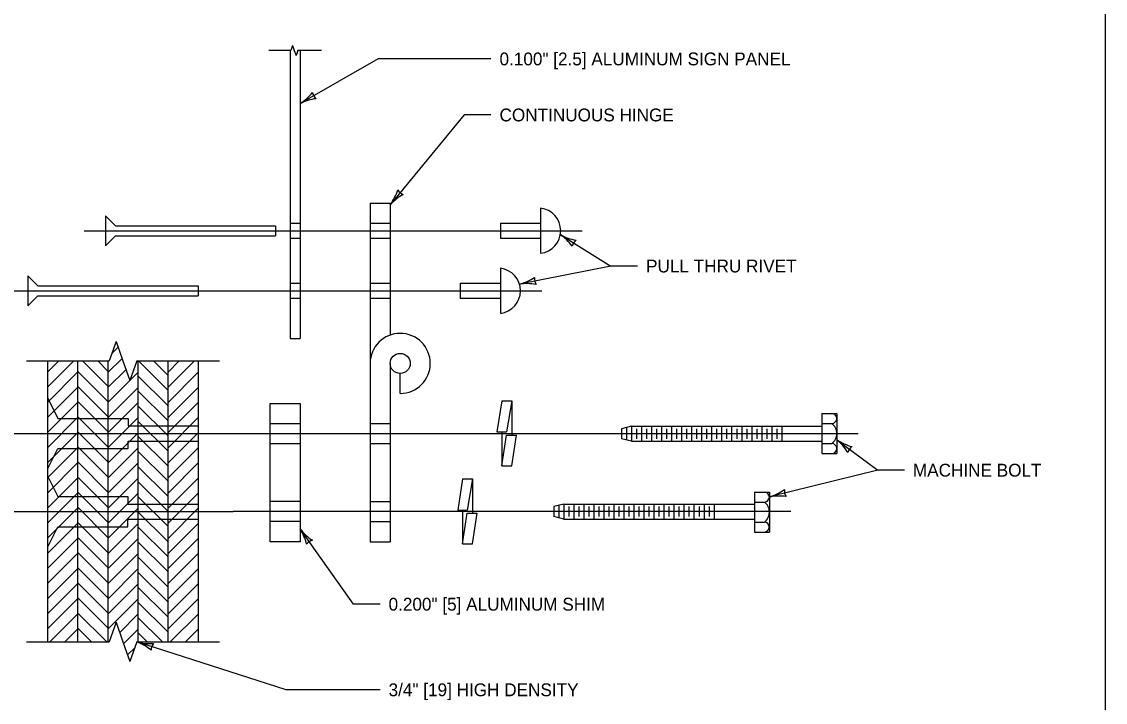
# Model space of a CAD drawing. Extents: x 49991.4 to 50021, y 49987.6 to 50011.4.
# Drawn here: x 50011.68 to 50016.75, y 49990.65 to 49993.84 of the extents above; entities that cross this region are included whole.
import ezdxf

# ---------------------------------------------------------------- set-up
doc = ezdxf.new("R2010")
doc.units = 0
for name, color, linetype in [('Level 1', 7, 'Continuous'), ('Level 2', 7, 'Continuous'), ('Level 3', 7, 'Continuous'), ('Level 4', 7, 'Continuous'), ('Level 5', 7, 'Continuous'), ('Level 6', 7, 'Continuous')]:
    doc.layers.add(name, color=color, linetype=linetype)

msp = doc.modelspace()

# ---------------------------------------------------------------- linework, layer by layer
at = {"layer": 'Level 1'}
for p, q in [((50012.9345, 49993.7046), (50012.9345, 49992.3569)), ((50012.9813, 49993.7046), (50012.9813, 49992.3569)), ((50013.3091, 49992.9898), (50013.4029, 49992.9898)), ((50013.3091, 49992.9898), (50013.3091, 49991.4053)), ((50013.4029, 49992.9898), (50013.4029, 49992.3724)), ((50012.0697, 49992.9311), (50012.0697, 49992.8609)), ((50012.1166, 49992.8843), (50012.0697, 49992.9311)), ((50014.1071, 49992.9664), (50014.1071, 49992.7554)), ((50012.1166, 49992.8843), (50012.8666, 49992.8843)), ((50012.8666, 49992.8843), (50012.8666, 49992.8375)), ((50012.981, 49992.896), (50012.9822, 49992.896)), ((50013.9186, 49992.896), (50014.1071, 49992.896)), ((50013.9186, 49992.896), (50013.9186, 49992.8257)), ((50012.0697, 49992.8609), (50012.0697, 49992.7906)), ((50012.1166, 49992.8375), (50012.0697, 49992.7906)), ((50012.1166, 49992.8375), (50012.8666, 49992.8375)), ((50013.9186, 49992.8257), (50014.1071, 49992.8257)), ((50013.9186, 49992.6851), (50013.9186, 49992.4742)), ((50011.7071, 49992.6499), (50011.7071, 49992.5796)), ((50011.754, 49992.6031), (50011.7071, 49992.6499)), ((50011.7071, 49992.5796), (50011.7071, 49992.5093)), ((50011.754, 49992.6031), (50012.504, 49992.6031)), ((50012.504, 49992.6031), (50012.504, 49992.5562)), ((50013.73, 49992.6148), (50013.9186, 49992.6148)), ((50013.73, 49992.6148), (50013.7311, 49992.5444)), ((50011.754, 49992.5562), (50011.7071, 49992.5093)), ((50011.754, 49992.5562), (50012.504, 49992.5562)), ((50013.7311, 49992.5444), (50013.9186, 49992.5444)), ((50013.7311, 49992.5444), (50013.9186, 49992.5444)), ((50012.0997, 49992.2861), (50012.1293, 49992.3157)), ((50012.9345, 49992.3569), (50012.9813, 49992.3569)), ((50011.8005, 49990.9364), (50011.8005, 49992.2512)), ((50011.8005, 49992.1297), (50011.922, 49992.2512)), ((50011.8005, 49992.2004), (50011.8513, 49992.2512)), ((50011.9412, 49990.9364), (50011.9412, 49992.2512)), ((50012.0818, 49992.1327), (50011.9633, 49992.2512)), ((50012.0818, 49992.2034), (50012.034, 49992.2512)), ((50012.0818, 49992.1975), (50012.1478, 49992.2635)), ((50012.0818, 49992.2512), (50012.0818, 49990.9364)), ((50012.2224, 49992.2512), (50012.2224, 49990.9364)), ((50012.363, 49992.1122), (50012.224, 49992.2512)), ((50012.363, 49992.1829), (50012.2947, 49992.2512)), ((50012.363, 49992.1987), (50012.4155, 49992.2512)), ((50012.363, 49992.128), (50012.4862, 49992.2512)), ((50012.363, 49990.9364), (50012.363, 49992.2512)), ((50012.5037, 49992.2512), (50012.5037, 49990.9364)), ((50013.4029, 49992.2398), (50013.4029, 49991.4053)), ((50011.8005, 49992.059), (50011.9412, 49992.1997)), ((50012.0818, 49992.062), (50011.9412, 49992.2026)), ((50012.0818, 49992.1268), (50012.1663, 49992.2113)), ((50012.0818, 49992.0561), (50012.2224, 49992.1967)), ((50012.363, 49992.0415), (50012.2224, 49992.1821)), ((50012.363, 49992.0573), (50012.5037, 49992.198)), ((50013.4498, 49992.0991), (50013.4498, 49992.1929)), ((50011.8005, 49991.9883), (50011.9412, 49992.129)), ((50012.0818, 49991.9913), (50011.9412, 49992.1319)), ((50012.0818, 49991.9854), (50012.2224, 49992.126)), ((50012.363, 49991.9866), (50012.5037, 49992.1273)), ((50012.363, 49991.9708), (50012.2224, 49992.1114)), ((50013.9251, 49992.0652), (50013.9025, 49991.9187)), ((50013.9251, 49992.0652), (50013.9719, 49992.0652)), ((50013.9719, 49992.0652), (50013.9476, 49991.9187)), ((50013.9719, 49992.0652), (50013.9719, 49991.9044)), ((50011.8005, 49991.9176), (50011.9412, 49992.0583)), ((50012.0818, 49991.9206), (50011.9412, 49992.0612)), ((50012.0818, 49991.9147), (50012.2224, 49992.0553)), ((50012.363, 49991.9001), (50012.2224, 49992.0407)), ((50012.363, 49991.9159), (50012.5037, 49992.0566)), ((50012.8404, 49991.4053), (50012.8404, 49992.0523)), ((50012.8404, 49992.0523), (50012.981, 49992.0523)), ((50012.981, 49992.0523), (50012.981, 49991.4053)), ((50011.8005, 49991.8469), (50011.9412, 49991.9876)), ((50012.0818, 49991.8498), (50011.9412, 49991.9904)), ((50012.0818, 49991.844), (50012.2224, 49991.9846)), ((50012.363, 49991.8294), (50012.2224, 49991.97)), ((50012.363, 49991.8452), (50012.5037, 49991.9859)), ((50015.423, 49992.0054), (50015.423, 49991.8179)), ((50015.423, 49992.0054), (50015.4933, 49992.0054)), ((50015.4933, 49992.0054), (50015.4933, 49991.8179)), ((50011.8005, 49991.7762), (50011.9412, 49991.9169)), ((50012.0818, 49991.7791), (50011.9412, 49991.9197)), ((50012.0818, 49991.7733), (50012.2224, 49991.9139)), ((50012.363, 49991.7744), (50012.5037, 49991.9151)), ((50013.9025, 49991.9187), (50013.9476, 49991.9187)), ((50013.9251, 49991.9187), (50013.9251, 49991.7605)), ((50014.5324, 49991.9457), (50014.4855, 49991.934)), ((50014.4855, 49991.934), (50014.4855, 49991.8871)), ((50014.509, 49991.9399), (50014.509, 49991.8812)), ((50014.509, 49991.934), (50014.509, 49991.8871)), ((50014.5324, 49991.9457), (50014.5324, 49991.8753)), ((50014.5324, 49991.9457), (50014.5324, 49991.8753)), ((50014.5324, 49991.9457), (50015.423, 49991.9457)), ((50014.5558, 49991.934), (50014.5558, 49991.8871)), ((50014.5792, 49991.9457), (50014.5792, 49991.8753)), ((50014.6027, 49991.934), (50014.6027, 49991.8871)), ((50014.6261, 49991.9457), (50014.6261, 49991.8753)), ((50014.6496, 49991.934), (50014.6496, 49991.8871)), ((50014.673, 49991.9457), (50014.673, 49991.8753)), ((50014.6965, 49991.934), (50014.6965, 49991.8871)), ((50014.7199, 49991.9457), (50014.7199, 49991.8753)), ((50014.7433, 49991.934), (50014.7433, 49991.8871)), ((50014.7667, 49991.9457), (50014.7667, 49991.8753)), ((50014.7902, 49991.934), (50014.7902, 49991.8871)), ((50014.8136, 49991.9457), (50014.8136, 49991.8753)), ((50014.8371, 49991.934), (50014.8371, 49991.8871)), ((50014.8605, 49991.9457), (50014.8605, 49991.8753)), ((50014.884, 49991.934), (50014.884, 49991.8871)), ((50014.9074, 49991.9457), (50014.9074, 49991.8753)), ((50014.9308, 49991.934), (50014.9308, 49991.8871)), ((50014.9542, 49991.9457), (50014.9542, 49991.8753)), ((50014.9777, 49991.934), (50014.9777, 49991.8871)), ((50015.0011, 49991.9457), (50015.0011, 49991.8753)), ((50015.0246, 49991.934), (50015.0246, 49991.8871)), ((50015.048, 49991.9457), (50015.048, 49991.8753)), ((50015.0715, 49991.934), (50015.0715, 49991.8871)), ((50015.0949, 49991.9457), (50015.0949, 49991.8753)), ((50015.1183, 49991.934), (50015.1183, 49991.8871)), ((50015.1417, 49991.9457), (50015.1417, 49991.8753)), ((50015.1652, 49991.934), (50015.1652, 49991.8871)), ((50015.1886, 49991.9457), (50015.1886, 49991.8753)), ((50015.2121, 49991.934), (50015.2121, 49991.8871)), ((50015.2355, 49991.9457), (50015.2355, 49991.8753)), ((50015.423, 49991.9585), (50015.4699, 49991.9585)), ((50012.363, 49991.7586), (50012.2224, 49991.8992)), ((50013.9251, 49991.7605), (50013.9473, 49991.9044)), ((50013.9473, 49991.9044), (50013.9941, 49991.9044)), ((50013.9719, 49991.7605), (50013.9941, 49991.9044)), ((50014.5324, 49991.8753), (50014.4855, 49991.8871)), ((50014.5324, 49991.8753), (50015.423, 49991.8753)), ((50015.423, 49991.8648), (50015.4699, 49991.8648)), ((50011.8005, 49991.7054), (50011.9412, 49991.8461)), ((50012.0818, 49991.7084), (50011.9412, 49991.849)), ((50012.0818, 49991.7025), (50012.2224, 49991.8431)), ((50012.363, 49991.6879), (50012.2224, 49991.8285)), ((50012.363, 49991.7037), (50012.5037, 49991.8444)), ((50015.423, 49991.8179), (50015.4933, 49991.8179)), ((50011.8005, 49991.6347), (50011.9412, 49991.7754)), ((50012.0818, 49991.6377), (50011.9412, 49991.7783)), ((50012.0818, 49991.6318), (50012.2224, 49991.7724)), ((50012.363, 49991.6172), (50012.2224, 49991.7578)), ((50012.363, 49991.633), (50012.5037, 49991.7737)), ((50013.9251, 49991.7605), (50013.9719, 49991.7605)), ((50012.0818, 49991.567), (50011.9412, 49991.7076)), ((50011.8005, 49991.564), (50011.9412, 49991.7047)), ((50012.0818, 49991.5611), (50012.2224, 49991.7017)), ((50012.363, 49991.5465), (50012.2224, 49991.6871)), ((50012.363, 49991.5623), (50012.5037, 49991.703)), ((50013.7413, 49991.6995), (50013.7187, 49991.553)), ((50013.7413, 49991.6995), (50013.7881, 49991.6995)), ((50013.7881, 49991.6995), (50013.7638, 49991.553)), ((50013.7881, 49991.6995), (50013.7881, 49991.5387)), ((50011.8005, 49991.4933), (50011.9412, 49991.634)), ((50012.0818, 49991.4963), (50011.9412, 49991.6369)), ((50012.0818, 49991.4904), (50012.2224, 49991.631)), ((50012.363, 49991.4758), (50012.2224, 49991.6164)), ((50012.363, 49991.4916), (50012.5037, 49991.6323)), ((50015.1075, 49991.6376), (50015.1075, 49991.4501)), ((50015.1075, 49991.6376), (50015.1779, 49991.6376)), ((50015.1779, 49991.6376), (50015.1779, 49991.4501)), ((50011.8005, 49991.4226), (50011.9412, 49991.5633)), ((50012.0818, 49991.4256), (50011.9412, 49991.5662)), ((50012.0818, 49991.4197), (50012.2224, 49991.5603)), ((50012.363, 49991.4209), (50012.5037, 49991.5616)), ((50014.2154, 49991.5811), (50014.1685, 49991.5694)), ((50014.1685, 49991.5694), (50014.1685, 49991.5225)), ((50014.192, 49991.5753), (50014.192, 49991.5166)), ((50014.2154, 49991.5811), (50014.2154, 49991.5107)), ((50014.2154, 49991.5811), (50015.106, 49991.5811)), ((50014.2389, 49991.5694), (50014.2389, 49991.5225)), ((50014.2623, 49991.5811), (50014.2623, 49991.5107)), ((50014.2858, 49991.5694), (50014.2858, 49991.5225)), ((50014.3092, 49991.5811), (50014.3092, 49991.5107)), ((50014.3326, 49991.5694), (50014.3326, 49991.5225)), ((50014.356, 49991.5811), (50014.356, 49991.5107)), ((50014.3795, 49991.5694), (50014.3795, 49991.5225)), ((50014.4029, 49991.5811), (50014.4029, 49991.5107)), ((50014.4264, 49991.5694), (50014.4264, 49991.5225)), ((50014.4498, 49991.5811), (50014.4498, 49991.5107)), ((50014.4733, 49991.5694), (50014.4733, 49991.5225)), ((50014.4967, 49991.5811), (50014.4967, 49991.5107)), ((50014.5201, 49991.5694), (50014.5201, 49991.5225)), ((50014.5435, 49991.5811), (50014.5435, 49991.5107)), ((50014.567, 49991.5694), (50014.567, 49991.5225)), ((50014.5904, 49991.5811), (50014.5904, 49991.5107)), ((50014.6139, 49991.5694), (50014.6139, 49991.5225)), ((50014.6373, 49991.5811), (50014.6373, 49991.5107)), ((50014.6608, 49991.5694), (50014.6608, 49991.5225)), ((50014.6842, 49991.5811), (50014.6842, 49991.5107)), ((50014.7076, 49991.5694), (50014.7076, 49991.5225)), ((50014.731, 49991.5811), (50014.731, 49991.5107)), ((50014.7545, 49991.5694), (50014.7545, 49991.5225)), ((50014.7779, 49991.5811), (50014.7779, 49991.5107)), ((50014.8014, 49991.5694), (50014.8014, 49991.5225)), ((50014.8248, 49991.5811), (50014.8248, 49991.5107)), ((50014.8483, 49991.5694), (50014.8483, 49991.5225)), ((50014.8717, 49991.5811), (50014.8717, 49991.5107)), ((50014.8951, 49991.5694), (50014.8951, 49991.5225)), ((50014.9185, 49991.5811), (50014.9185, 49991.5107)), ((50015.1075, 49991.5907), (50015.1544, 49991.5907)), ((50012.363, 49991.4051), (50012.2224, 49991.5457)), ((50013.7187, 49991.553), (50013.7638, 49991.553)), ((50013.7413, 49991.553), (50013.7413, 49991.3948)), ((50013.7413, 49991.3948), (50013.7635, 49991.5387)), ((50013.7635, 49991.5387), (50013.8103, 49991.5387)), ((50013.7881, 49991.3948), (50013.8103, 49991.5387)), ((50014.2154, 49991.5107), (50014.1685, 49991.5225)), ((50014.2154, 49991.5107), (50015.106, 49991.5107)), ((50011.8005, 49991.3519), (50011.9412, 49991.4926)), ((50012.0818, 49991.3549), (50011.9412, 49991.4955)), ((50012.0818, 49991.349), (50012.2224, 49991.4896)), ((50012.363, 49991.3344), (50012.2224, 49991.475)), ((50012.363, 49991.3502), (50012.5037, 49991.4909)), ((50015.1075, 49991.497), (50015.1544, 49991.497)), ((50011.8005, 49991.2812), (50011.9412, 49991.4219)), ((50012.0818, 49991.2842), (50011.9412, 49991.4248)), ((50012.0818, 49991.2783), (50012.2224, 49991.4189)), ((50012.363, 49991.2637), (50012.2224, 49991.4043)), ((50012.363, 49991.2795), (50012.5037, 49991.4202)), ((50012.981, 49991.4053), (50012.8404, 49991.4053)), ((50013.3091, 49991.4053), (50013.4029, 49991.4053)), ((50015.1075, 49991.4501), (50015.1779, 49991.4501)), ((50012.0818, 49991.2135), (50011.9412, 49991.3541)), ((50013.7413, 49991.3948), (50013.7881, 49991.3948)), ((50011.8005, 49991.2105), (50011.9412, 49991.3512)), ((50012.0818, 49991.2076), (50012.2224, 49991.3482)), ((50012.363, 49991.193), (50012.2224, 49991.3336)), ((50012.363, 49991.2088), (50012.5037, 49991.3495)), ((50011.8005, 49991.1398), (50011.9412, 49991.2805)), ((50012.0818, 49991.1427), (50011.9412, 49991.2833)), ((50012.0818, 49991.1369), (50012.2224, 49991.2775)), ((50012.363, 49991.1223), (50012.2224, 49991.2629)), ((50012.363, 49991.1381), (50012.5037, 49991.2788)), ((50011.8005, 49991.0691), (50011.9412, 49991.2098)), ((50012.0818, 49991.072), (50011.9412, 49991.2126)), ((50012.0818, 49991.0662), (50012.2224, 49991.2068)), ((50012.363, 49991.0674), (50012.5037, 49991.2081)), ((50012.363, 49991.0515), (50012.2224, 49991.1921)), ((50011.8005, 49990.9983), (50011.9412, 49991.139)), ((50012.0818, 49991.0013), (50011.9412, 49991.1419)), ((50012.0818, 49990.9954), (50012.2224, 49991.136)), ((50012.363, 49990.981), (50012.2224, 49991.1214)), ((50012.363, 49990.9967), (50012.5037, 49991.1374)), ((50011.8093, 49990.9364), (50011.9412, 49991.0683)), ((50012.076, 49990.9364), (50011.9412, 49991.0712)), ((50012.1368, 49990.9797), (50012.2224, 49991.0653)), ((50012.3367, 49990.9364), (50012.2224, 49991.0507)), ((50012.3734, 49990.9364), (50012.5037, 49991.0667)), ((50011.88, 49990.9364), (50011.9412, 49990.9976)), ((50012.0053, 49990.9364), (50011.9412, 49991.0005)), ((50012.1553, 49990.9275), (50012.2224, 49990.9946)), ((50012.266, 49990.9364), (50012.2224, 49990.98)), ((50012.4441, 49990.9364), (50012.5037, 49990.996)), ((50012.1738, 49990.8753), (50012.207, 49990.9085))]:
    msp.add_line(p, q, dxfattribs=at)
msp.add_lwpolyline([(49999.3835, 49998.9992), (50016.7501, 49998.9992), (50016.7501, 49987.7988), (49999.3835, 49987.7988)], close=True, dxfattribs=at)
msp.add_circle((50013.4498, 49992.2398), 0.0469, dxfattribs=at)
for centre, radius, start, end in [((50014.0946, 49992.8609), 0.1062, 276.7432, 83.2568), ((50013.9061, 49992.5796), 0.1062, 276.7705, 83.2295), ((50013.4498, 49992.2398), 0.1407, 270, 180), ((50015.4696, 49991.982), 0.0234, 270.5326, 89.4674), ((50015.4348, 49991.9117), 0.0585, 306.7973, 53.2026), ((50015.4695, 49991.8413), 0.0234, 270.9766, 89.0235), ((50015.1542, 49991.6142), 0.0234, 270.5326, 89.4674), ((50015.1193, 49991.5439), 0.0585, 306.7973, 53.2026), ((50015.154, 49991.4736), 0.0234, 270.9766, 89.0235)]:
    msp.add_arc(centre, radius, start, end, dxfattribs=at)
at = {"layer": 'Level 3'}
for p, q in [((50013.3464, 49993.665), (50012.9813, 49993.4557)), ((50013.8746, 49993.665), (50013.3464, 49993.665)), ((50013.7497, 49993.4027), (50013.4029, 49992.9825)), ((50013.8746, 49993.4027), (50013.7497, 49993.4027)), ((50014.1992, 49992.8425), (50014.4356, 49992.6954)), ((50014.4356, 49992.6954), (50014.0076, 49992.6109)), ((50014.5605, 49992.6954), (50014.4356, 49992.6954)), ((50015.4933, 49991.8821), (50015.6847, 49991.7399)), ((50015.6847, 49991.7399), (50015.1779, 49991.6145)), ((50015.8096, 49991.7399), (50015.6847, 49991.7399)), ((50013.2304, 49991.1125), (50012.981, 49991.4648)), ((50013.3553, 49991.1125), (50013.2304, 49991.1125)), ((50012.9163, 49990.7119), (50012.2168, 49990.936)), ((50013.3553, 49990.7119), (50012.9163, 49990.7119))]:
    msp.add_line(p, q, dxfattribs=at)
for centre, radius, start, end in [((50012.8556, 49993.6519), 0.233, 302.6559, 321.9057), ((50013.0925, 49993.5195), 0.0548, 191.9674, 227.6898), ((50013.0838, 49993.2584), 0.2223, 97.2846, 117.4681), ((50013.2161, 49993.1218), 0.233, 323.2906, 342.5405), ((50013.5684, 49992.834), 0.2223, 117.9193, 138.1028), ((50013.4845, 49993.0814), 0.0548, 212.6021, 248.3245), ((50014.0741, 49992.6587), 0.2223, 35.5635, 55.747), ((50014.3124, 49993.0461), 0.233, 240.9348, 260.1847), ((50014.3081, 49992.7747), 0.0548, 130.2463, 165.9687), ((50013.9512, 49992.837), 0.233, 284.0004, 303.2503), ((50014.1334, 49992.6357), 0.0548, 173.3119, 209.0343), ((50014.0417, 49992.3912), 0.2223, 78.6291, 98.8126), ((50015.3535, 49991.7093), 0.2223, 30.8438, 51.0273), ((50015.6229, 49992.0758), 0.233, 236.2151, 255.4649), ((50015.5962, 49991.8056), 0.0548, 125.5266, 161.249), ((50015.1109, 49991.8376), 0.233, 286.7244, 305.9742), ((50015.2224, 49991.3967), 0.2223, 81.3531, 101.5366), ((50015.3024, 49991.6453), 0.0548, 176.0359, 211.7582), ((50012.7944, 49991.3439), 0.2223, 12.7544, 32.9379), ((50013.1643, 49991.6086), 0.233, 218.1257, 237.3756), ((50013.0551, 49991.3602), 0.0548, 107.4372, 143.1596), ((50012.1403, 49990.7273), 0.2223, 49.6891, 69.8726), ((50012.2768, 49991.1612), 0.233, 255.0604, 274.3103), ((50012.3389, 49990.8969), 0.0548, 144.3719, 180.0943)]:
    msp.add_arc(centre, radius, start, end, dxfattribs=at)
at = {"layer": 'Level 4'}
for p, q in [((50012.9345, 49992.896), (50012.981, 49992.896)), ((50013.3081, 49992.896), (50013.4013, 49992.896)), ((50012.9345, 49992.8257), (50012.981, 49992.8257)), ((50013.3081, 49992.8257), (50013.4029, 49992.8257)), ((50012.9345, 49992.6148), (50012.981, 49992.6148)), ((50013.3081, 49992.6148), (50013.4013, 49992.6148)), ((50012.9345, 49992.5444), (50012.981, 49992.5444)), ((50013.3092, 49992.5444), (50013.4013, 49992.5444)), ((50011.8007, 49992.0763), (50011.8476, 49991.9826)), ((50011.8476, 49991.9826), (50012.1757, 49991.9826)), ((50012.1757, 49991.9826), (50012.1757, 49991.9472)), ((50012.1757, 49991.9472), (50012.5037, 49991.9472)), ((50012.8404, 49991.9585), (50012.9798, 49991.9585)), ((50013.3091, 49991.9585), (50013.4029, 49991.9585)), ((50012.1757, 49991.8412), (50012.1757, 49991.8761)), ((50012.1757, 49991.8761), (50012.5037, 49991.8761)), ((50012.8404, 49991.8648), (50012.981, 49991.8648)), ((50013.3091, 49991.8648), (50013.4038, 49991.8648)), ((50011.8007, 49991.7475), (50011.8476, 49991.8412)), ((50011.8476, 49991.8412), (50012.1757, 49991.8412)), ((50011.8004, 49991.7107), (50011.8473, 49991.6169)), ((50011.8473, 49991.6169), (50012.1754, 49991.6169)), ((50012.1754, 49991.6169), (50012.1754, 49991.5814)), ((50012.1754, 49991.5814), (50012.5037, 49991.5814)), ((50012.981, 49991.5928), (50012.8404, 49991.5928)), ((50013.3091, 49991.5928), (50013.4029, 49991.5928)), ((50012.1754, 49991.4755), (50012.1754, 49991.5103)), ((50012.1754, 49991.5103), (50012.5037, 49991.5103)), ((50011.8004, 49991.3818), (50011.8473, 49991.4755)), ((50011.8473, 49991.4755), (50012.1754, 49991.4755)), ((50012.981, 49991.499), (50012.8404, 49991.499)), ((50013.3091, 49991.499), (50013.4029, 49991.499))]:
    msp.add_line(p, q, dxfattribs=at)
at = {"layer": 'Level 5'}
for p, q in [((50011.9697, 49992.8609), (50014.3008, 49992.8609)), ((50011.6071, 49992.5796), (50014.1123, 49992.5796)), ((50011.2893, 49991.9116), (50014.0869, 49991.9116)), ((50014.0869, 49991.9116), (50015.5933, 49991.9116)), ((50011.4709, 49991.5459), (50012.6672, 49991.5459)), ((50015.2779, 49991.5459), (50012.6672, 49991.5459))]:
    msp.add_line(p, q, dxfattribs=at)
at = {"layer": 'Level 6'}
for p, q in [((50012.9378, 49993.7046), (50012.8345, 49993.7046)), ((50012.9459, 49993.7274), (50012.9378, 49993.7046)), ((50012.9459, 49993.7274), (50012.954, 49993.7046)), ((50012.954, 49993.7046), (50012.9621, 49993.6818)), ((50012.9702, 49993.7046), (50012.9621, 49993.6818)), ((50013.0813, 49993.7046), (50012.9702, 49993.7046)), ((50012.1197, 49992.3426), (50012.0873, 49992.2512)), ((50012.1197, 49992.3426), (50012.1521, 49992.2512)), ((50011.7005, 49992.2512), (50012.0873, 49992.2512)), ((50012.1521, 49992.2512), (50012.1845, 49992.1598)), ((50012.2169, 49992.2512), (50012.1845, 49992.1598)), ((50012.2169, 49992.2512), (50012.6037, 49992.2512)), ((50012.1197, 49991.0278), (50012.0873, 49990.9364)), ((50012.1197, 49991.0278), (50012.1521, 49990.9364)), ((50011.7005, 49990.9364), (50012.0873, 49990.9364)), ((50012.1521, 49990.9364), (50012.1845, 49990.845)), ((50012.2169, 49990.9364), (50012.1845, 49990.845)), ((50012.2169, 49990.9364), (50012.6037, 49990.9364))]:
    msp.add_line(p, q, dxfattribs=at)

# ---------------------------------------------------------------- texts
at = {"layer": 'Level 2'}
for s, p in [('0.100" [2.5] ALUMINUM SIGN PANEL', (50013.9146, 49993.635)), ('CONTINUOUS HINGE', (50013.9146, 49993.3727)), ('PULL THRU RIVET', (50014.6005, 49992.6654)), ('MACHINE BOLT', (50015.8496, 49991.7099)), ('0.200" [5] ALUMINUM SHIM', (50013.3953, 49991.0825)), ('3/4" [19] HIGH DENSITY', (50013.3953, 49990.6819))]:
    msp.add_text(s, height=0.06, dxfattribs=at).set_placement(p)

doc.saveas('drawing.dxf')
